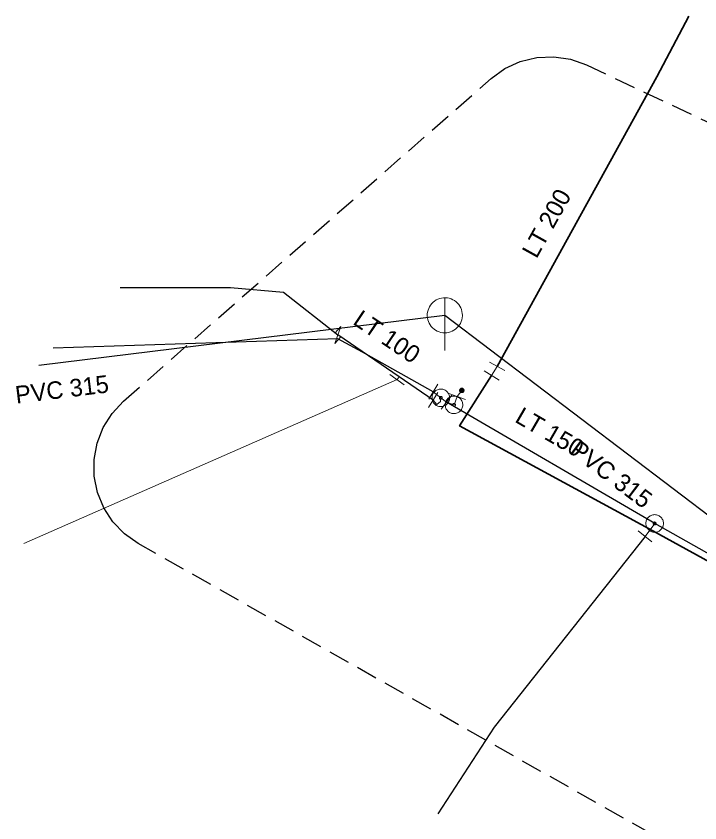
# Model space of a CAD drawing. Extents: x -749365 to -748625, y -965388 to -964881.
# Drawn here: x -749365.16 to -749326.21, y -964927.15 to -964881.18 of the extents above; entities that cross this region are included whole.
import ezdxf

# ---------------------------------------------------------------- set-up
doc = ezdxf.new("R2010")
doc.units = 0
doc.header["$LTSCALE"] = 0.4
doc.linetypes.add('MEDIUM_DASHED', pattern=[4.5, 3, -1.5])
for name, color, linetype, lineweight in [('1', 7, 'MEDIUM_DASHED', 25), ('13', 7, 'Continuous', 13), ('14', 7, 'Continuous', 13), ('17', 7, 'Continuous', 25), ('22', 7, 'Continuous', 13), ('34', 7, 'Continuous', 13), ('47', 7, 'Continuous', 13), ('9', 7, 'Continuous', 13)]:
    doc.layers.add(name, color=color, linetype=linetype, lineweight=lineweight)

msp = doc.modelspace()

# ---------------------------------------------------------------- linework, layer by layer
at = {"layer": '1'}
msp.add_lwpolyline([(-748913.896, -965162.751), (-749358.2, -964911.234), (-749358.98, -964910.689), (-749359.642, -964910.006), (-749360.163, -964909.209), (-749360.523, -964908.329), (-749360.711, -964907.396), (-749360.718, -964906.445), (-749360.545, -964905.509), (-749360.198, -964904.624), (-749359.689, -964903.82), (-749359.037, -964903.126), (-749338.098, -964884.732), (-749337.314, -964884.168), (-749336.437, -964883.765), (-749335.498, -964883.538), (-749334.533, -964883.496), (-749333.578, -964883.64), (-749332.669, -964883.965), (-749106.184, -964990.559)], dxfattribs=at)
at = {"layer": '13'}
msp.add_line((-749343.457, -964901.895), (-749364.725, -964911.228), dxfattribs=at)
at = {"layer": '14', "lineweight": 25}
for p, q in [((-749363.861, -964901.078), (-749340.739, -964898.23)), ((-749340.739, -964898.23), (-749318.67, -964914.98))]:
    msp.add_line(p, q, dxfattribs=at)
at = {"layer": '14'}
for p, q in [((-749338.07, -964901.664), (-749337.75, -964901.143)), ((-749343.341, -964901.733), (-749343.457, -964901.895)), ((-749340.967, -964902.933), (-749341.396, -964902.583)), ((-749340.215, -964903.334), (-749340.035, -964902.856)), ((-749340.035, -964902.856), (-749339.77, -964902.51)), ((-749340.967, -964902.933), (-749340.641, -964903.184)), ((-749340.641, -964903.184), (-749340.215, -964903.334)), ((-749328.782, -964910.09), (-749329.331, -964910.827))]:
    msp.add_line(p, q, dxfattribs=at)
msp.add_lwpolyline([(-749341.399, -964903.059), (-749341.192, -964903.309), (-749340.986, -964903.146), (-749340.967, -964902.933)], dxfattribs=at)
at = {"layer": '17'}
msp.add_line((-749328.782, -964910.09), (-749340.641, -964903.184), dxfattribs=at)
at = {"layer": '17', "lineweight": 35}
for points in [[(-749326.836, -964881.184), (-749328.66, -964884.649), (-749337.75, -964901.143)], [(-749338.07, -964901.664), (-749339.897, -964904.533), (-749328.89, -964910.512), (-749320.106, -964915.328), (-749306.348, -964923.318), (-749302.22, -964925.541), (-749292.258, -964930.514), (-749280.577, -964937.024), (-749272.375, -964941.575), (-749255.349, -964950.855), (-749231.471, -964964.54), (-749222.21, -964969.832), (-749218.876, -964969.25), (-749196.521, -964982.106)]]:
    msp.add_lwpolyline(points, dxfattribs=at)
at = {"layer": '17'}
for points in [[(-749359.239, -964896.648), (-749352.943, -964896.638), (-749349.936, -964896.92), (-749346.829, -964899.351)], [(-749341.396, -964902.583), (-749345.214, -964900.454), (-749346.832, -964899.563), (-749363.056, -964900.102)], [(-749341.399, -964903.059), (-749343.341, -964901.733), (-749346.829, -964899.351)], [(-749306.274, -964922.687), (-749320.025, -964915.03), (-749328.782, -964910.09)], [(-749329.331, -964910.827), (-749337.919, -964921.69), (-749341.138, -964926.639)]]:
    msp.add_lwpolyline(points, dxfattribs=at)
at = {"layer": '22'}
msp.add_line((-749340.739, -964900.23), (-749340.738, -964897.23), dxfattribs=at)
msp.add_lwpolyline([(-749339.739, -964898.23), (-749339.744, -964898.121), (-749339.762, -964898.013), (-749339.792, -964897.907), (-749339.832, -964897.806), (-749339.884, -964897.709), (-749339.946, -964897.619), (-749340.018, -964897.536), (-749340.098, -964897.462), (-749340.186, -964897.396), (-749340.28, -964897.341), (-749340.38, -964897.296), (-749340.485, -964897.263), (-749340.592, -964897.241), (-749340.701, -964897.231), (-749340.811, -964897.233), (-749340.919, -964897.247), (-749341.026, -964897.272), (-749341.129, -964897.309), (-749341.227, -964897.358), (-749341.319, -964897.416), (-749341.405, -964897.485), (-749341.482, -964897.562), (-749341.551, -964897.648), (-749341.61, -964897.74), (-749341.658, -964897.838), (-749341.695, -964897.941), (-749341.721, -964898.048), (-749341.735, -964898.156), (-749341.738, -964898.266), (-749341.728, -964898.375), (-749341.707, -964898.482), (-749341.673, -964898.586), (-749341.629, -964898.686), (-749341.574, -964898.781), (-749341.508, -964898.869), (-749341.434, -964898.949), (-749341.351, -964899.021), (-749341.261, -964899.083), (-749341.165, -964899.135), (-749341.063, -964899.176), (-749340.958, -964899.206), (-749340.85, -964899.224), (-749340.74, -964899.23), (-749340.631, -964899.224), (-749340.523, -964899.206), (-749340.418, -964899.177), (-749340.316, -964899.136), (-749340.219, -964899.084), (-749340.129, -964899.022), (-749340.046, -964898.951), (-749339.971, -964898.871), (-749339.906, -964898.783), (-749339.85, -964898.689), (-749339.806, -964898.589), (-749339.772, -964898.485), (-749339.75, -964898.377), (-749339.74, -964898.268)], close=True, dxfattribs=at)
at = {"layer": '34'}
for p, q in [((-749337.311, -964901.383), (-749338.187, -964900.901)), ((-749338.496, -964901.402), (-749337.644, -964901.926)), ((-749343.05, -964902.186), (-749343.862, -964901.603)), ((-749341.651, -964903.012), (-749341.139, -964902.153)), ((-749341.666, -964903.481), (-749341.13, -964902.637)), ((-749340.336, -964902.787), (-749340.946, -964903.58)), ((-749340.503, -964902.68), (-749339.567, -964903.032)), ((-749328.938, -964911.136), (-749329.722, -964910.516))]:
    msp.add_line(p, q, dxfattribs=at)
at = {"layer": '47'}
msp.add_line((-749347, -964899.83), (-749346.656, -964899.453), dxfattribs=at)
msp.add_lwpolyline([(-749347, -964899.83), (-749346.657, -964898.871), (-749347.001, -964899.248)], dxfattribs=at)
for points in [[(-749340.709, -964902.504), (-749340.755, -964902.48), (-749340.804, -964902.46), (-749340.854, -964902.446), (-749340.905, -964902.436), (-749340.958, -964902.433), (-749341.011, -964902.435), (-749341.062, -964902.443), (-749341.113, -964902.455), (-749341.162, -964902.473), (-749341.209, -964902.495), (-749341.254, -964902.523), (-749341.295, -964902.556), (-749341.332, -964902.592), (-749341.366, -964902.632), (-749341.395, -964902.675), (-749341.419, -964902.721), (-749341.439, -964902.77), (-749341.454, -964902.821), (-749341.463, -964902.871), (-749341.466, -964902.924), (-749341.464, -964902.977), (-749341.457, -964903.029), (-749341.444, -964903.08), (-749341.427, -964903.129), (-749341.404, -964903.175), (-749341.376, -964903.22), (-749341.343, -964903.261), (-749341.307, -964903.298), (-749341.267, -964903.332), (-749341.224, -964903.361), (-749341.178, -964903.385), (-749341.129, -964903.405), (-749341.079, -964903.42), (-749341.028, -964903.429), (-749340.975, -964903.432), (-749340.923, -964903.431), (-749340.871, -964903.424), (-749340.82, -964903.411), (-749340.77, -964903.393), (-749340.724, -964903.37), (-749340.679, -964903.342), (-749340.638, -964903.31), (-749340.601, -964903.273), (-749340.567, -964903.233), (-749340.538, -964903.19), (-749340.514, -964903.144), (-749340.494, -964903.095), (-749340.479, -964903.045), (-749340.47, -964902.994), (-749340.467, -964902.941), (-749340.468, -964902.889), (-749340.476, -964902.838), (-749340.488, -964902.787), (-749340.507, -964902.737), (-749340.529, -964902.69), (-749340.557, -964902.645), (-749340.589, -964902.605), (-749340.626, -964902.567), (-749340.666, -964902.533)], [(-749340.924, -964902.862), (-749340.932, -964902.858), (-749340.94, -964902.855), (-749340.948, -964902.853), (-749340.956, -964902.851), (-749340.965, -964902.851), (-749340.974, -964902.851), (-749340.982, -964902.852), (-749340.991, -964902.854), (-749340.998, -964902.857), (-749341.006, -964902.861), (-749341.014, -964902.866), (-749341.021, -964902.871), (-749341.026, -964902.877), (-749341.032, -964902.883), (-749341.037, -964902.89), (-749341.041, -964902.898), (-749341.044, -964902.906), (-749341.046, -964902.914), (-749341.048, -964902.922), (-749341.048, -964902.931), (-749341.048, -964902.94), (-749341.047, -964902.948), (-749341.045, -964902.957), (-749341.042, -964902.965), (-749341.038, -964902.972), (-749341.033, -964902.98), (-749341.028, -964902.987), (-749341.022, -964902.992), (-749341.016, -964902.998), (-749341.009, -964903.003), (-749341.001, -964903.007), (-749340.993, -964903.01), (-749340.985, -964903.012), (-749340.977, -964903.014), (-749340.968, -964903.014), (-749340.96, -964903.015), (-749340.951, -964903.013), (-749340.942, -964903.011), (-749340.934, -964903.008), (-749340.927, -964903.004), (-749340.919, -964902.999), (-749340.912, -964902.994), (-749340.907, -964902.988), (-749340.901, -964902.982), (-749340.896, -964902.975), (-749340.892, -964902.967), (-749340.889, -964902.959), (-749340.887, -964902.951), (-749340.885, -964902.943), (-749340.885, -964902.934), (-749340.884, -964902.926), (-749340.886, -964902.917), (-749340.888, -964902.908), (-749340.891, -964902.901), (-749340.895, -964902.893), (-749340.9, -964902.885), (-749340.905, -964902.878), (-749340.911, -964902.873), (-749340.917, -964902.867)], [(-749339.743, -964903.5), (-749339.729, -964903.45), (-749339.719, -964903.398), (-749339.715, -964903.346), (-749339.716, -964903.294), (-749339.723, -964903.242), (-749339.736, -964903.191), (-749339.753, -964903.142), (-749339.776, -964903.095), (-749339.803, -964903.05), (-749339.835, -964903.008), (-749339.871, -964902.97), (-749339.911, -964902.937), (-749339.954, -964902.907), (-749340, -964902.882), (-749340.048, -964902.862), (-749340.098, -964902.848), (-749340.15, -964902.838), (-749340.203, -964902.834), (-749340.254, -964902.835), (-749340.306, -964902.842), (-749340.357, -964902.855), (-749340.407, -964902.872), (-749340.454, -964902.895), (-749340.499, -964902.921), (-749340.54, -964902.954), (-749340.578, -964902.99), (-749340.612, -964903.03), (-749340.641, -964903.073), (-749340.666, -964903.119), (-749340.686, -964903.167), (-749340.7, -964903.217), (-749340.71, -964903.269), (-749340.715, -964903.321), (-749340.713, -964903.373), (-749340.706, -964903.425), (-749340.694, -964903.476), (-749340.677, -964903.526), (-749340.654, -964903.573), (-749340.627, -964903.618), (-749340.594, -964903.659), (-749340.558, -964903.697), (-749340.519, -964903.731), (-749340.475, -964903.76), (-749340.429, -964903.785), (-749340.381, -964903.805), (-749340.331, -964903.819), (-749340.279, -964903.829), (-749340.228, -964903.834), (-749340.175, -964903.832), (-749340.123, -964903.825), (-749340.072, -964903.813), (-749340.023, -964903.795), (-749339.976, -964903.773), (-749339.931, -964903.745), (-749339.889, -964903.713), (-749339.851, -964903.677), (-749339.818, -964903.638), (-749339.788, -964903.594), (-749339.763, -964903.548)], [(-749340.137, -964903.361), (-749340.134, -964903.352), (-749340.133, -964903.344), (-749340.133, -964903.336), (-749340.133, -964903.327), (-749340.134, -964903.318), (-749340.136, -964903.31), (-749340.139, -964903.302), (-749340.142, -964903.294), (-749340.147, -964903.287), (-749340.152, -964903.28), (-749340.158, -964903.274), (-749340.165, -964903.268), (-749340.172, -964903.264), (-749340.179, -964903.259), (-749340.187, -964903.256), (-749340.196, -964903.253), (-749340.204, -964903.252), (-749340.212, -964903.252), (-749340.221, -964903.252), (-749340.23, -964903.253), (-749340.238, -964903.255), (-749340.246, -964903.258), (-749340.254, -964903.261), (-749340.262, -964903.266), (-749340.268, -964903.271), (-749340.274, -964903.277), (-749340.28, -964903.284), (-749340.284, -964903.291), (-749340.289, -964903.298), (-749340.292, -964903.306), (-749340.295, -964903.315), (-749340.296, -964903.323), (-749340.296, -964903.331), (-749340.296, -964903.34), (-749340.295, -964903.349), (-749340.294, -964903.356), (-749340.29, -964903.365), (-749340.287, -964903.373), (-749340.282, -964903.381), (-749340.277, -964903.387), (-749340.271, -964903.393), (-749340.264, -964903.399), (-749340.257, -964903.403), (-749340.25, -964903.408), (-749340.242, -964903.411), (-749340.233, -964903.414), (-749340.225, -964903.415), (-749340.217, -964903.415), (-749340.208, -964903.415), (-749340.199, -964903.414), (-749340.192, -964903.413), (-749340.183, -964903.409), (-749340.175, -964903.406), (-749340.168, -964903.401), (-749340.161, -964903.396), (-749340.155, -964903.39), (-749340.149, -964903.383), (-749340.145, -964903.376), (-749340.14, -964903.369)], [(-749328.282, -964910.09), (-749328.285, -964910.038), (-749328.293, -964909.985), (-749328.307, -964909.936), (-749328.325, -964909.887), (-749328.349, -964909.84), (-749328.378, -964909.796), (-749328.411, -964909.755), (-749328.448, -964909.718), (-749328.488, -964909.686), (-749328.532, -964909.657), (-749328.579, -964909.632), (-749328.628, -964909.615), (-749328.678, -964909.601), (-749328.73, -964909.593), (-749328.782, -964909.59), (-749328.834, -964909.593), (-749328.886, -964909.601), (-749328.937, -964909.615), (-749328.985, -964909.632), (-749329.032, -964909.657), (-749329.076, -964909.686), (-749329.117, -964909.718), (-749329.154, -964909.755), (-749329.187, -964909.796), (-749329.215, -964909.84), (-749329.239, -964909.887), (-749329.258, -964909.936), (-749329.271, -964909.985), (-749329.279, -964910.038), (-749329.282, -964910.09), (-749329.279, -964910.142), (-749329.271, -964910.194), (-749329.258, -964910.245), (-749329.239, -964910.293), (-749329.215, -964910.34), (-749329.187, -964910.384), (-749329.154, -964910.424), (-749329.117, -964910.462), (-749329.076, -964910.495), (-749329.032, -964910.522), (-749328.985, -964910.547), (-749328.937, -964910.566), (-749328.886, -964910.578), (-749328.834, -964910.587), (-749328.782, -964910.59), (-749328.73, -964910.587), (-749328.678, -964910.578), (-749328.628, -964910.566), (-749328.579, -964910.547), (-749328.532, -964910.522), (-749328.488, -964910.495), (-749328.448, -964910.462), (-749328.411, -964910.424), (-749328.378, -964910.384), (-749328.349, -964910.34), (-749328.325, -964910.293), (-749328.307, -964910.245), (-749328.293, -964910.194), (-749328.285, -964910.142)], [(-749328.7, -964910.09), (-749328.7, -964910.081), (-749328.702, -964910.073), (-749328.704, -964910.065), (-749328.707, -964910.056), (-749328.711, -964910.049), (-749328.716, -964910.042), (-749328.721, -964910.034), (-749328.727, -964910.029), (-749328.734, -964910.024), (-749328.741, -964910.019), (-749328.749, -964910.015), (-749328.757, -964910.012), (-749328.765, -964910.01), (-749328.773, -964910.007), (-749328.782, -964910.007), (-749328.791, -964910.007), (-749328.799, -964910.01), (-749328.807, -964910.012), (-749328.815, -964910.015), (-749328.823, -964910.019), (-749328.83, -964910.024), (-749328.837, -964910.029), (-749328.843, -964910.034), (-749328.849, -964910.042), (-749328.853, -964910.049), (-749328.857, -964910.056), (-749328.86, -964910.065), (-749328.862, -964910.073), (-749328.864, -964910.081), (-749328.864, -964910.09), (-749328.864, -964910.098), (-749328.862, -964910.107), (-749328.86, -964910.115), (-749328.857, -964910.123), (-749328.853, -964910.13), (-749328.849, -964910.137), (-749328.843, -964910.145), (-749328.837, -964910.151), (-749328.83, -964910.157), (-749328.823, -964910.161), (-749328.815, -964910.164), (-749328.807, -964910.168), (-749328.799, -964910.169), (-749328.791, -964910.172), (-749328.782, -964910.172), (-749328.773, -964910.172), (-749328.765, -964910.169), (-749328.757, -964910.168), (-749328.749, -964910.164), (-749328.741, -964910.161), (-749328.734, -964910.157), (-749328.727, -964910.151), (-749328.721, -964910.145), (-749328.716, -964910.137), (-749328.711, -964910.13), (-749328.707, -964910.123), (-749328.704, -964910.115), (-749328.702, -964910.107), (-749328.7, -964910.098)]]:
    msp.add_lwpolyline(points, close=True, dxfattribs=at)
at = {"layer": '9'}
for points in [[(-749339.896, -964902.51), (-749339.896, -964902.523), (-749339.894, -964902.536), (-749339.891, -964902.549), (-749339.886, -964902.561), (-749339.88, -964902.573), (-749339.873, -964902.584), (-749339.865, -964902.594), (-749339.855, -964902.604), (-749339.845, -964902.612), (-749339.834, -964902.619), (-749339.822, -964902.625), (-749339.81, -964902.63), (-749339.797, -964902.633), (-749339.784, -964902.635), (-749339.771, -964902.637), (-749339.758, -964902.636), (-749339.745, -964902.634), (-749339.732, -964902.631), (-749339.72, -964902.626), (-749339.708, -964902.62), (-749339.697, -964902.613), (-749339.687, -964902.605), (-749339.677, -964902.595), (-749339.669, -964902.585), (-749339.662, -964902.574), (-749339.656, -964902.562), (-749339.651, -964902.55), (-749339.648, -964902.537), (-749339.646, -964902.524), (-749339.644, -964902.511), (-749339.645, -964902.498), (-749339.647, -964902.485), (-749339.65, -964902.472), (-749339.655, -964902.46), (-749339.661, -964902.448), (-749339.668, -964902.437), (-749339.676, -964902.427), (-749339.686, -964902.417), (-749339.696, -964902.409), (-749339.707, -964902.402), (-749339.719, -964902.396), (-749339.731, -964902.391), (-749339.744, -964902.388), (-749339.757, -964902.386), (-749339.77, -964902.385), (-749339.783, -964902.385), (-749339.796, -964902.387), (-749339.809, -964902.39), (-749339.821, -964902.395), (-749339.833, -964902.401), (-749339.844, -964902.408), (-749339.854, -964902.416), (-749339.864, -964902.426), (-749339.872, -964902.436), (-749339.879, -964902.447), (-749339.885, -964902.459), (-749339.89, -964902.471), (-749339.893, -964902.484), (-749339.895, -964902.497)], [(-749339.876, -964902.51), (-749339.877, -964902.521), (-749339.875, -964902.532), (-749339.872, -964902.543), (-749339.868, -964902.553), (-749339.863, -964902.563), (-749339.857, -964902.572), (-749339.85, -964902.581), (-749339.842, -964902.589), (-749339.833, -964902.596), (-749339.824, -964902.602), (-749339.814, -964902.607), (-749339.804, -964902.611), (-749339.793, -964902.614), (-749339.782, -964902.617), (-749339.771, -964902.617), (-749339.76, -964902.617), (-749339.749, -964902.615), (-749339.738, -964902.612), (-749339.728, -964902.608), (-749339.718, -964902.603), (-749339.709, -964902.597), (-749339.7, -964902.59), (-749339.692, -964902.582), (-749339.685, -964902.573), (-749339.679, -964902.564), (-749339.674, -964902.554), (-749339.67, -964902.544), (-749339.667, -964902.533), (-749339.665, -964902.522), (-749339.664, -964902.511), (-749339.664, -964902.5), (-749339.666, -964902.489), (-749339.669, -964902.478), (-749339.673, -964902.468), (-749339.678, -964902.458), (-749339.684, -964902.449), (-749339.691, -964902.44), (-749339.699, -964902.432), (-749339.708, -964902.425), (-749339.717, -964902.419), (-749339.727, -964902.414), (-749339.737, -964902.41), (-749339.748, -964902.407), (-749339.759, -964902.405), (-749339.77, -964902.405), (-749339.781, -964902.404), (-749339.792, -964902.406), (-749339.803, -964902.409), (-749339.813, -964902.413), (-749339.823, -964902.418), (-749339.832, -964902.424), (-749339.841, -964902.431), (-749339.849, -964902.439), (-749339.856, -964902.448), (-749339.862, -964902.457), (-749339.867, -964902.467), (-749339.871, -964902.477), (-749339.874, -964902.488), (-749339.876, -964902.499)], [(-749339.857, -964902.51), (-749339.857, -964902.519), (-749339.856, -964902.528), (-749339.853, -964902.537), (-749339.85, -964902.545), (-749339.846, -964902.553), (-749339.841, -964902.561), (-749339.835, -964902.568), (-749339.829, -964902.574), (-749339.822, -964902.58), (-749339.814, -964902.585), (-749339.806, -964902.589), (-749339.798, -964902.592), (-749339.789, -964902.595), (-749339.78, -964902.596), (-749339.771, -964902.598), (-749339.762, -964902.597), (-749339.753, -964902.596), (-749339.744, -964902.593), (-749339.736, -964902.59), (-749339.728, -964902.586), (-749339.72, -964902.581), (-749339.713, -964902.575), (-749339.707, -964902.569), (-749339.701, -964902.562), (-749339.696, -964902.554), (-749339.692, -964902.546), (-749339.689, -964902.538), (-749339.686, -964902.529), (-749339.685, -964902.52), (-749339.683, -964902.511), (-749339.684, -964902.502), (-749339.685, -964902.493), (-749339.688, -964902.484), (-749339.691, -964902.476), (-749339.695, -964902.468), (-749339.7, -964902.46), (-749339.706, -964902.453), (-749339.712, -964902.447), (-749339.719, -964902.441), (-749339.727, -964902.436), (-749339.735, -964902.432), (-749339.743, -964902.429), (-749339.752, -964902.426), (-749339.761, -964902.425), (-749339.77, -964902.424), (-749339.779, -964902.424), (-749339.788, -964902.425), (-749339.797, -964902.428), (-749339.805, -964902.431), (-749339.813, -964902.435), (-749339.821, -964902.44), (-749339.828, -964902.446), (-749339.834, -964902.452), (-749339.84, -964902.459), (-749339.845, -964902.467), (-749339.849, -964902.475), (-749339.852, -964902.483), (-749339.855, -964902.492), (-749339.856, -964902.501)], [(-749339.837, -964902.51), (-749339.837, -964902.517), (-749339.836, -964902.524), (-749339.835, -964902.531), (-749339.832, -964902.537), (-749339.829, -964902.543), (-749339.825, -964902.549), (-749339.821, -964902.555), (-749339.816, -964902.56), (-749339.81, -964902.564), (-749339.804, -964902.568), (-749339.798, -964902.571), (-749339.792, -964902.574), (-749339.785, -964902.575), (-749339.778, -964902.578), (-749339.771, -964902.578), (-749339.764, -964902.578), (-749339.757, -964902.576), (-749339.75, -964902.575), (-749339.744, -964902.572), (-749339.737, -964902.569), (-749339.732, -964902.565), (-749339.726, -964902.561), (-749339.721, -964902.556), (-749339.717, -964902.55), (-749339.713, -964902.544), (-749339.71, -964902.538), (-749339.707, -964902.532), (-749339.705, -964902.525), (-749339.704, -964902.518), (-749339.703, -964902.511), (-749339.703, -964902.504), (-749339.704, -964902.497), (-749339.706, -964902.49), (-749339.709, -964902.484), (-749339.712, -964902.477), (-749339.716, -964902.472), (-749339.72, -964902.466), (-749339.725, -964902.461), (-749339.731, -964902.457), (-749339.736, -964902.453), (-749339.743, -964902.45), (-749339.749, -964902.447), (-749339.756, -964902.445), (-749339.763, -964902.444), (-749339.77, -964902.444), (-749339.777, -964902.444), (-749339.784, -964902.444), (-749339.791, -964902.446), (-749339.797, -964902.449), (-749339.803, -964902.452), (-749339.809, -964902.456), (-749339.815, -964902.46), (-749339.82, -964902.465), (-749339.824, -964902.471), (-749339.828, -964902.476), (-749339.831, -964902.483), (-749339.834, -964902.489), (-749339.835, -964902.496), (-749339.837, -964902.503)], [(-749339.817, -964902.51), (-749339.817, -964902.515), (-749339.817, -964902.52), (-749339.816, -964902.525), (-749339.814, -964902.529), (-749339.812, -964902.534), (-749339.809, -964902.538), (-749339.806, -964902.541), (-749339.802, -964902.545), (-749339.799, -964902.548), (-749339.795, -964902.551), (-749339.79, -964902.553), (-749339.786, -964902.555), (-749339.781, -964902.556), (-749339.776, -964902.558), (-749339.771, -964902.558), (-749339.766, -964902.558), (-749339.761, -964902.557), (-749339.756, -964902.556), (-749339.752, -964902.554), (-749339.747, -964902.552), (-749339.743, -964902.549), (-749339.739, -964902.546), (-749339.736, -964902.542), (-749339.733, -964902.539), (-749339.73, -964902.535), (-749339.728, -964902.53), (-749339.726, -964902.526), (-749339.725, -964902.521), (-749339.724, -964902.516), (-749339.723, -964902.511), (-749339.723, -964902.506), (-749339.724, -964902.501), (-749339.725, -964902.496), (-749339.727, -964902.492), (-749339.729, -964902.487), (-749339.732, -964902.483), (-749339.735, -964902.479), (-749339.738, -964902.476), (-749339.742, -964902.473), (-749339.746, -964902.47), (-749339.751, -964902.468), (-749339.755, -964902.466), (-749339.76, -964902.465), (-749339.765, -964902.464), (-749339.77, -964902.464), (-749339.775, -964902.464), (-749339.78, -964902.465), (-749339.785, -964902.465), (-749339.789, -964902.467), (-749339.794, -964902.469), (-749339.798, -964902.472), (-749339.801, -964902.475), (-749339.805, -964902.478), (-749339.808, -964902.482), (-749339.811, -964902.486), (-749339.813, -964902.491), (-749339.815, -964902.495), (-749339.816, -964902.5), (-749339.817, -964902.505)], [(-749339.797, -964902.51), (-749339.797, -964902.513), (-749339.798, -964902.516), (-749339.797, -964902.518), (-749339.796, -964902.521), (-749339.795, -964902.524), (-749339.793, -964902.526), (-749339.791, -964902.528), (-749339.789, -964902.53), (-749339.787, -964902.532), (-749339.785, -964902.534), (-749339.782, -964902.536), (-749339.779, -964902.537), (-749339.777, -964902.537), (-749339.774, -964902.538), (-749339.771, -964902.538), (-749339.768, -964902.538), (-749339.765, -964902.538), (-749339.762, -964902.537), (-749339.76, -964902.536), (-749339.757, -964902.535), (-749339.755, -964902.533), (-749339.752, -964902.531), (-749339.75, -964902.529), (-749339.749, -964902.527), (-749339.747, -964902.525), (-749339.746, -964902.522), (-749339.744, -964902.519), (-749339.744, -964902.517), (-749339.743, -964902.514), (-749339.742, -964902.511), (-749339.743, -964902.508), (-749339.743, -964902.505), (-749339.744, -964902.502), (-749339.745, -964902.5), (-749339.746, -964902.497), (-749339.748, -964902.495), (-749339.749, -964902.492), (-749339.751, -964902.49), (-749339.754, -964902.489), (-749339.756, -964902.487), (-749339.759, -964902.486), (-749339.761, -964902.485), (-749339.764, -964902.484), (-749339.767, -964902.484), (-749339.77, -964902.483), (-749339.773, -964902.484), (-749339.776, -964902.483), (-749339.778, -964902.485), (-749339.781, -964902.485), (-749339.784, -964902.486), (-749339.786, -964902.488), (-749339.788, -964902.489), (-749339.79, -964902.491), (-749339.792, -964902.494), (-749339.794, -964902.496), (-749339.795, -964902.499), (-749339.796, -964902.501), (-749339.797, -964902.504), (-749339.797, -964902.507)], [(-749339.778, -964902.51), (-749339.778, -964902.512), (-749339.778, -964902.512), (-749339.777, -964902.512), (-749339.777, -964902.514), (-749339.778, -964902.515), (-749339.776, -964902.515), (-749339.776, -964902.515), (-749339.776, -964902.517), (-749339.776, -964902.517), (-749339.775, -964902.518), (-749339.773, -964902.518), (-749339.773, -964902.518), (-749339.773, -964902.519), (-749339.771, -964902.519), (-749339.771, -964902.519), (-749339.77, -964902.519), (-749339.769, -964902.519), (-749339.769, -964902.518), (-749339.768, -964902.518), (-749339.766, -964902.518), (-749339.766, -964902.517), (-749339.766, -964902.517), (-749339.765, -964902.516), (-749339.765, -964902.516), (-749339.763, -964902.515), (-749339.763, -964902.514), (-749339.762, -964902.513), (-749339.762, -964902.513), (-749339.762, -964902.512), (-749339.762, -964902.511), (-749339.762, -964902.51), (-749339.762, -964902.509), (-749339.762, -964902.509), (-749339.763, -964902.508), (-749339.763, -964902.507), (-749339.764, -964902.506), (-749339.764, -964902.506), (-749339.765, -964902.505), (-749339.765, -964902.505), (-749339.766, -964902.504), (-749339.767, -964902.504), (-749339.768, -964902.503), (-749339.768, -964902.503), (-749339.769, -964902.503), (-749339.77, -964902.503), (-749339.771, -964902.503), (-749339.772, -964902.503), (-749339.772, -964902.503), (-749339.773, -964902.504), (-749339.774, -964902.503), (-749339.775, -964902.505), (-749339.775, -964902.505), (-749339.776, -964902.505), (-749339.776, -964902.505), (-749339.777, -964902.507), (-749339.777, -964902.508), (-749339.777, -964902.509), (-749339.778, -964902.509), (-749339.778, -964902.51)]]:
    msp.add_lwpolyline(points, close=True, dxfattribs=at)

# ---------------------------------------------------------------- texts
at = {"layer": '1'}
for s, rotation, p in [('LT 200', 61, (-749335.515, -964895.047)), ('LT 100', 326, (-749346.035, -964898.699)), ('PVC 315 ', 7, (-749365.147, -964903.27)), ('LT 150', 330, (-749336.808, -964904.276)), ('PVC 315 ', 323, (-749333.692, -964906.07))]:
    msp.add_text(s, height=1, rotation=rotation, dxfattribs=at).set_placement(p)

doc.saveas('drawing.dxf')
